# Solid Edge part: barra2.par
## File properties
Author: there
Template: iso metric part.par
Last saved by: there
Revision: 4
Application: Solid Edge
Precisión: 0.990
Username: there
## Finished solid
Body 1: solid body, 8 faces, 16 edges, 8 vertices.
  Faces by surface: cylinder 4, plane 4
  Edges by curve: circle 8, line 8
Bounding box of the edges (mm): 12.500 x 3.000 x 72.500, from (-6.25, -3, -66.25) to (6.25, 0, 6.25).
Cylindrical faces by radius (mm): R3.2 x2, R6.25 x2
Planar faces by outward normal: +x 1, +y 1, -x 1, -y 1
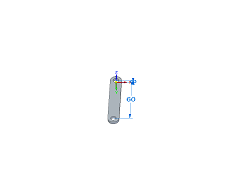
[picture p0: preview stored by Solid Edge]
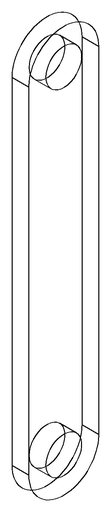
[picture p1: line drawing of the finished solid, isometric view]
